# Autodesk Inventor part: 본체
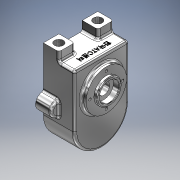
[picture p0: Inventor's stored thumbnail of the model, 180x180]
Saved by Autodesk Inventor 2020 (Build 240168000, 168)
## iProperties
Created: 2024-03
Part Number: 본체
Material: 알루미늄 6061
Document SubType Name: Modeling
Designer: 1강의실14
Density: 2.7 g/cm^3
Appearance: 알루미늄 - 평지
Mass: 642.952 g
Surface Area: 391.444 cm^2
Volume: 238.13 cm^3
Author: 1강의실14
## Parameters: d0 = 103 mm, d3 = 0, d4 = 35 mm, d5 = 35 mm, d6 = 52 mm, d7 = 6 mm, d8 = 0, d9 = 32 mm, d10 = 4 mm, d11 = 0, d12 = 25 mm, d13 = 7.3 mm, d14 = 0, d15 = 35 mm, d16 = 36 mm, d17 = 33 mm, d18 = 36 mm, d19 = 28 mm, d22 = 0, d26 = 0, d27 = 15 mm, d29 = 0, d30 = 7 mm, d31 = 60 deg, d32 = 90 deg, d33 = 42 mm, d34 = 3.242 mm, d35 = 8 mm, d36 = 4 mm, d37 = 2 mm, d38 = 90 deg, d40 = 118 deg, d42 = 360 deg, d44 = 3.5 mm, d45 = 0.7 mm, d46 = 30 deg, d47 = 90 deg, d48 = 51.5 mm, d51 = 0, d52 = 9 mm, d53 = 85 mm, d54 = 4.134 mm, d56 = 4 mm, d57 = 2 mm, d58 = 90 deg, d59 = 12 mm, d60 = 118 deg, d89 = 1 mm, d90 = 2 mm, d91 = 45 deg, d92 = 3 mm, d109 = 51.5 mm, d110 = 25 mm, d111 = 51.5 mm, d112 = 8 mm, d114 = 51.5 mm, d115 = 6 mm, d116 = 0, d117 = 0, d122 = 12 mm, d123 = 0, d128 = 10.5 mm, d129 = 11 mm, d130 = 0.62479 mm, d131 = 10.589 mm, d132 = 4 mm, d133 = 2 mm, d134 = 90 deg, d135 = 16 mm, d136 = 118 deg, d137 = 3 mm, d139 = 0.5 mm, d140 = 0
